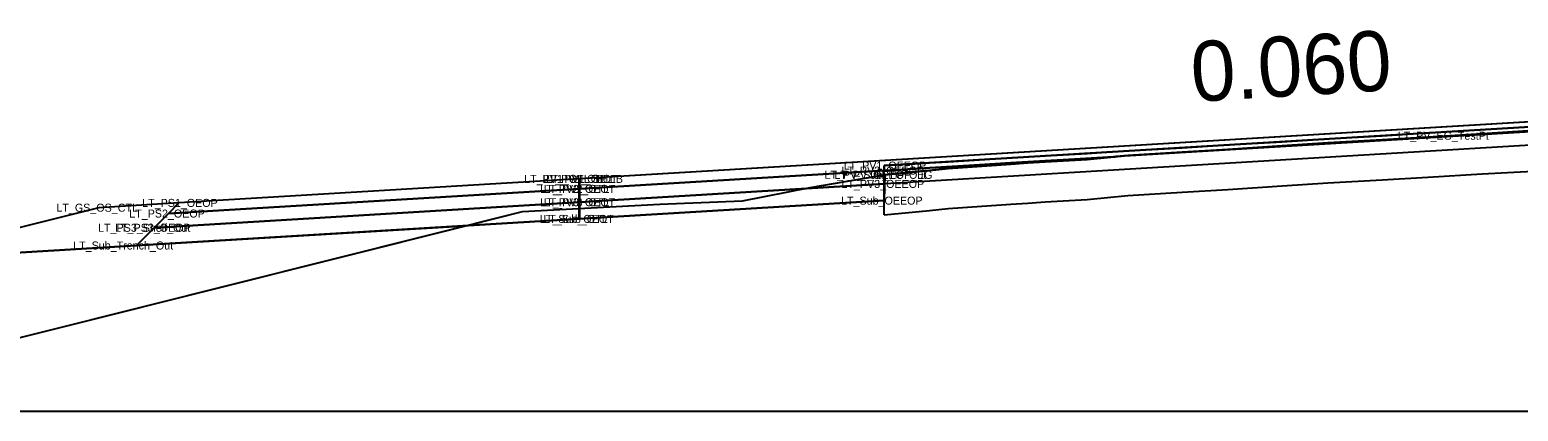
# Model space of a CAD drawing. Extents: x 2177029 to 2201446, y 59897 to 78390.
# Drawn here: x 2200162.99 to 2200200.19, y 66907.31 to 66916.84 of the extents above; entities that cross this region are included whole.
import ezdxf

# ---------------------------------------------------------------- set-up
doc = ezdxf.new("R2010")
doc.units = 0
for name, color, linetype in [('Exist Cross Section Cell', 7, 'Continuous'), ('Exist PHM Roadway Shape', 7, 'Continuous'), ('Exist XS Ground Line', 7, 'Continuous'), ('Old_Level_11', 7, 'Continuous'), ('Prop CMT Conc Surface', 7, 'Continuous'), ('Prop CMT Concrete Structures', 7, 'Continuous'), ('Prop CMT Guardrail Graphics', 7, 'Continuous'), ('Prop CMT Pvmt Course 1', 7, 'Continuous'), ('Prop CMT Pvmt Course 1 CG', 7, 'Continuous'), ('Prop CMT Pvmt Course 2', 7, 'Continuous'), ('Prop CMT Pvmt Course 2 CG', 7, 'Continuous'), ('Prop CMT Pvmt Course 3', 7, 'Continuous'), ('Prop CMT Pvmt Course 4', 7, 'Continuous'), ('Prop CMT Pvmt Surface', 7, 'Continuous'), ('Prop CMT Pvmt Wedge Surface 1', 7, 'Continuous'), ('Prop CMT Slope Grass', 7, 'Continuous'), ('Prop CMT Subgrade Earthwork', 7, 'Continuous'), ('Prop Hatching', 7, 'Continuous'), ('Prop XS Side Slope Text', 7, 'Continuous'), ('Scratch_Level_0', 7, 'Continuous'), ('Scratch_Level_9', 7, 'Continuous')]:
    doc.layers.add(name, color=color, linetype=linetype)

msp = doc.modelspace()

# ---------------------------------------------------------------- linework, layer by layer
at = {"layer": 'Exist Cross Section Cell'}
msp.add_line((2200042.732, 66907.31), (2200242.732, 66907.31), dxfattribs=at)
at = {"layer": 'Exist XS Ground Line'}
msp.add_lwpolyline([(2200160.916, 66908.697), (2200175.302, 66912.295), (2200178.734, 66912.479), (2200180.806, 66912.563), (2200182.494, 66912.898), (2200184.345, 66913.213), (2200185.48, 66913.325), (2200185.944, 66913.374), (2200187.506, 66913.479), (2200187.931, 66913.509), (2200188.366, 66913.537), (2200189.421, 66913.599), (2200190.431, 66913.695), (2200191.791, 66913.778), (2200192.931, 66913.848), (2200194.29, 66913.94), (2200195.431, 66914.016), (2200196.79, 66914.09), (2200197.931, 66914.152), (2200199.289, 66914.238), (2200201.158, 66914.336)], dxfattribs=at)
at = {"layer": 'Prop CMT Conc Surface'}
for points in [[(2200212.732, 66915.147), (2200184.346, 66913.444)], [(2200184.346, 66913.319), (2200176.732, 66912.862)], [(2200184.346, 66913.444), (2200184.346, 66913.319)], [(2200176.732, 66912.862), (2200176.732, 66913.112)]]:
    msp.add_lwpolyline(points, dxfattribs=at)
at = {"layer": 'Prop CMT Concrete Structures'}
for p, q in [((2200212.732, 66915.272), (2200176.732, 66913.112)), ((2200176.732, 66913.112), (2200176.722, 66913.112))]:
    msp.add_line(p, q, dxfattribs=at)
at = {"layer": 'Prop CMT Guardrail Graphics'}
for points in [[(2200212.732, 66914.689), (2200176.732, 66912.529)], [(2200176.732, 66912.529), (2200176.732, 66913.112)]]:
    msp.add_lwpolyline(points, dxfattribs=at)
at = {"layer": 'Prop CMT Pvmt Course 1'}
for points in [[(2200184.346, 66913.319), (2200185.259, 66913.374), (2200185.48, 66913.387), (2200185.944, 66913.415), (2200187.506, 66913.509), (2200187.931, 66913.534), (2200188.366, 66913.561), (2200189.421, 66913.624), (2200190.113, 66913.665)], [(2200190.113, 66913.665), (2200189.421, 66913.599), (2200188.366, 66913.537), (2200187.931, 66913.509), (2200187.506, 66913.479), (2200185.944, 66913.374), (2200185.48, 66913.325), (2200185.259, 66913.302), (2200184.346, 66913.213)], [(2200184.346, 66913.213), (2200184.346, 66913.319)]]:
    msp.add_lwpolyline(points, dxfattribs=at)
at = {"layer": 'Prop CMT Pvmt Course 1 CG'}
for points in [[(2200176.722, 66912.528), (2200166.102, 66911.891)], [(2200176.722, 66912.112), (2200176.722, 66912.528)], [(2200165.658, 66911.448), (2200176.722, 66912.112)], [(2200166.102, 66911.891), (2200165.658, 66911.448)], [(2200166.102, 66911.891), (2200166.102, 66911.891)]]:
    msp.add_lwpolyline(points, dxfattribs=at)
at = {"layer": 'Prop CMT Pvmt Course 2'}
for points in [[(2200184.346, 66912.986), (2200176.732, 66912.529)], [(2200184.346, 66912.569), (2200184.346, 66912.986)], [(2200176.732, 66912.529), (2200176.722, 66912.528)], [(2200176.722, 66912.528), (2200176.722, 66912.112)], [(2200176.732, 66912.112), (2200184.346, 66912.569)], [(2200176.732, 66912.112), (2200176.732, 66912.529)], [(2200176.732, 66912.529), (2200176.732, 66912.112)], [(2200176.722, 66912.112), (2200176.732, 66912.112)]]:
    msp.add_lwpolyline(points, dxfattribs=at)
at = {"layer": 'Prop CMT Pvmt Course 2 CG'}
for points in [[(2200212.732, 66915.272), (2200176.732, 66913.112)], [(2200184.346, 66913.444), (2200212.732, 66915.147)], [(2200176.732, 66912.862), (2200184.346, 66913.319)], [(2200184.346, 66913.319), (2200184.346, 66913.444)], [(2200176.732, 66913.112), (2200176.724, 66913.112), (2200176.722, 66913.112)], [(2200176.722, 66913.112), (2200176.722, 66912.862)], [(2200176.722, 66912.862), (2200176.732, 66912.862)], [(2200176.732, 66912.862), (2200176.732, 66913.112)], [(2200176.732, 66913.112), (2200176.732, 66912.862)]]:
    msp.add_lwpolyline(points, dxfattribs=at)
at = {"layer": 'Prop CMT Pvmt Course 3'}
for points in [[(2200184.346, 66912.569), (2200184.36, 66913.214)], [(2200184.346, 66912.569), (2200176.732, 66912.112)], [(2200176.722, 66912.112), (2200165.658, 66911.448)], [(2200176.732, 66912.112), (2200176.722, 66912.112)], [(2200165.658, 66911.448), (2200159.459, 66911.076)]]:
    msp.add_lwpolyline(points, dxfattribs=at)
at = {"layer": 'Prop CMT Pvmt Course 4'}
msp.add_lwpolyline([(2200176.722, 66913.112), (2200166.721, 66912.512)], dxfattribs=at)
at = {"layer": 'Prop CMT Pvmt Surface'}
for points in [[(2200184.346, 66913.444), (2200185.259, 66913.499), (2200185.48, 66913.512), (2200185.944, 66913.54), (2200187.506, 66913.634), (2200187.931, 66913.659), (2200188.366, 66913.686), (2200189.421, 66913.749), (2200190.14, 66913.792), (2200190.431, 66913.809), (2200191.791, 66913.891), (2200192.931, 66913.959), (2200194.29, 66914.041), (2200195.431, 66914.109), (2200196.79, 66914.191), (2200197.931, 66914.259), (2200199.289, 66914.341), (2200200.431, 66914.409)], [(2200200.431, 66914.309), (2200199.289, 66914.238), (2200197.931, 66914.152), (2200196.79, 66914.09), (2200195.431, 66914.016), (2200194.29, 66913.94), (2200192.931, 66913.848), (2200191.791, 66913.778), (2200190.431, 66913.695), (2200190.14, 66913.668), (2200190.113, 66913.665), (2200189.421, 66913.624), (2200188.366, 66913.561), (2200187.931, 66913.534), (2200187.506, 66913.509), (2200185.944, 66913.415), (2200185.48, 66913.387), (2200185.259, 66913.374), (2200184.346, 66913.319)], [(2200184.346, 66913.319), (2200184.346, 66913.444)]]:
    msp.add_lwpolyline(points, dxfattribs=at)
at = {"layer": 'Prop CMT Pvmt Wedge Surface 1'}
for p, q in [((2200184.345, 66912.213), (2200184.345, 66913.213)), ((2200197.931, 66913.152), (2200199.289, 66913.238)), ((2200199.289, 66913.238), (2200201.158, 66913.336)), ((2200191.791, 66912.778), (2200192.931, 66912.848)), ((2200192.931, 66912.848), (2200194.29, 66912.94)), ((2200194.29, 66912.94), (2200195.431, 66913.016)), ((2200195.431, 66913.016), (2200196.79, 66913.09)), ((2200196.79, 66913.09), (2200197.931, 66913.152)), ((2200185.944, 66912.374), (2200187.506, 66912.479)), ((2200187.506, 66912.479), (2200187.931, 66912.509)), ((2200187.931, 66912.509), (2200188.366, 66912.537)), ((2200188.366, 66912.537), (2200189.421, 66912.599)), ((2200189.421, 66912.599), (2200190.431, 66912.695)), ((2200190.431, 66912.695), (2200191.791, 66912.778)), ((2200184.345, 66912.213), (2200185.48, 66912.325)), ((2200184.345, 66912.213), (2200184.345, 66912.213)), ((2200185.48, 66912.325), (2200185.944, 66912.374))]:
    msp.add_line(p, q, dxfattribs=at)
at = {"layer": 'Prop CMT Slope Grass'}
for points in [[(2200184.346, 66913.319), (2200176.732, 66912.862)], [(2200184.346, 66912.986), (2200184.346, 66913.319)], [(2200176.732, 66912.862), (2200176.722, 66912.862)], [(2200176.722, 66912.862), (2200176.722, 66912.528)], [(2200176.732, 66912.529), (2200184.346, 66912.986)], [(2200176.732, 66912.529), (2200176.732, 66912.862)], [(2200176.732, 66912.862), (2200176.732, 66912.529)], [(2200176.722, 66912.528), (2200176.732, 66912.529)]]:
    msp.add_lwpolyline(points, dxfattribs=at)
at = {"layer": 'Prop CMT Subgrade Earthwork'}
for points in [[(2200212.732, 66915.022), (2200176.732, 66912.862)], [(2200176.732, 66912.862), (2200176.732, 66913.112)]]:
    msp.add_lwpolyline(points, dxfattribs=at)
at = {"layer": 'Prop Hatching'}
msp.add_lwpolyline([(2200166.721, 66912.512), (2200164.722, 66912.392), (2200144.634, 66907.37)], dxfattribs=at)
at = {"layer": 'Prop XS Side Slope Text'}
msp.add_lwpolyline([(2200212.732, 66915.272), (2200176.722, 66913.112), (2200166.721, 66912.512), (2200164.722, 66912.392), (2200159.458, 66911.076), (2200165.658, 66911.448), (2200173.889, 66911.942), (2200175.302, 66912.295), (2200178.734, 66912.479), (2200180.806, 66912.563), (2200182.494, 66912.898), (2200184.36, 66913.214), (2200185.48, 66913.325), (2200185.944, 66913.374), (2200187.506, 66913.479), (2200187.931, 66913.509), (2200188.366, 66913.537), (2200189.421, 66913.599), (2200190.431, 66913.695), (2200191.791, 66913.778), (2200192.931, 66913.848), (2200194.29, 66913.94), (2200195.431, 66914.016), (2200196.79, 66914.09), (2200197.931, 66914.152), (2200199.289, 66914.238), (2200201.158, 66914.336)], dxfattribs=at)
for points in [[(2200178.734, 66912.479), (2200180.806, 66912.563), (2200182.494, 66912.898), (2200184.36, 66913.214), (2200184.346, 66912.569), (2200176.732, 66912.112), (2200173.889, 66911.942), (2200175.302, 66912.295)], [(2200156.242, 66908.04), (2200157.864, 66907.975), (2200160.916, 66908.697), (2200173.889, 66911.942), (2200165.658, 66911.448), (2200159.458, 66911.076), (2200149.04, 66908.472)]]:
    msp.add_lwpolyline(points, close=True, dxfattribs=at)
at = {"layer": 'Scratch_Level_0'}
for points in [[(2200176.722, 66912.862), (2200166.456, 66912.246), (2200166.102, 66911.891)], [(2200176.722, 66912.528), (2200176.722, 66912.862)], [(2200166.102, 66911.891), (2200176.722, 66912.528)]]:
    msp.add_lwpolyline(points, dxfattribs=at)
at = {"layer": 'Scratch_Level_9'}
for points in [[(2200176.722, 66913.112), (2200166.721, 66912.512), (2200166.456, 66912.246)], [(2200166.456, 66912.246), (2200176.722, 66912.862)], [(2200176.722, 66912.862), (2200176.722, 66913.112)]]:
    msp.add_lwpolyline(points, dxfattribs=at)

# ---------------------------------------------------------------- texts
at = {"layer": 'Exist PHM Roadway Shape'}
for s, p in [('LT_PV_EG_TestPt', (2200197.179, 66914.09)), ('LT_PV1_OEEOP', (2200183.333, 66913.344)), ('LT_PV1_OTL SE LB', (2200175.348, 66913.012)), ('LT_PV1_OEOT', (2200175.807, 66913.012)), ('LT_PV1_OTL', (2200175.894, 66913.012)), ('LT_PV_Sub_Tie_Out', (2200182.855, 66913.114)), ('LT_PV_OEEOP_EG', (2200183.1, 66913.113)), ('LT_PV2_OEEOP', (2200183.277, 66913.219)), ('LT_PV2_OEOT', (2200175.75, 66912.762)), ('LT_PV2_OTL', (2200175.837, 66912.762)), ('LT_PV3_OEEOP', (2200183.277, 66912.886)), ('LT_GS_OS_CTL', (2200163.659, 66912.292)), ('LT_PS1_OEOP', (2200165.802, 66912.412)), ('LT_PV3_OEOT', (2200175.75, 66912.429)), ('LT_PV3_OTL', (2200175.837, 66912.428)), ('LT_Sub_OEEOP', (2200183.267, 66912.469)), ('LT_PS2_OEOP', (2200165.479, 66912.146)), ('LT_Sub_OEOT', (2200175.74, 66912.012)), ('LT_Sub_OTL', (2200175.828, 66912.012)), ('LT_PS3_Shelf_Out', (2200164.7, 66911.791)), ('LT_PS3_OEOP', (2200165.125, 66911.791)), ('LT_Sub_Trench_Out', (2200164.078, 66911.348))]:
    msp.add_text(s, height=0.2, dxfattribs=at).set_placement(p)
at = {"layer": 'Old_Level_11'}
msp.add_text('0.060', height=1.5, rotation=3.4336, dxfattribs=at).set_placement((2200192.052, 66915.033))

doc.saveas('drawing.dxf')
